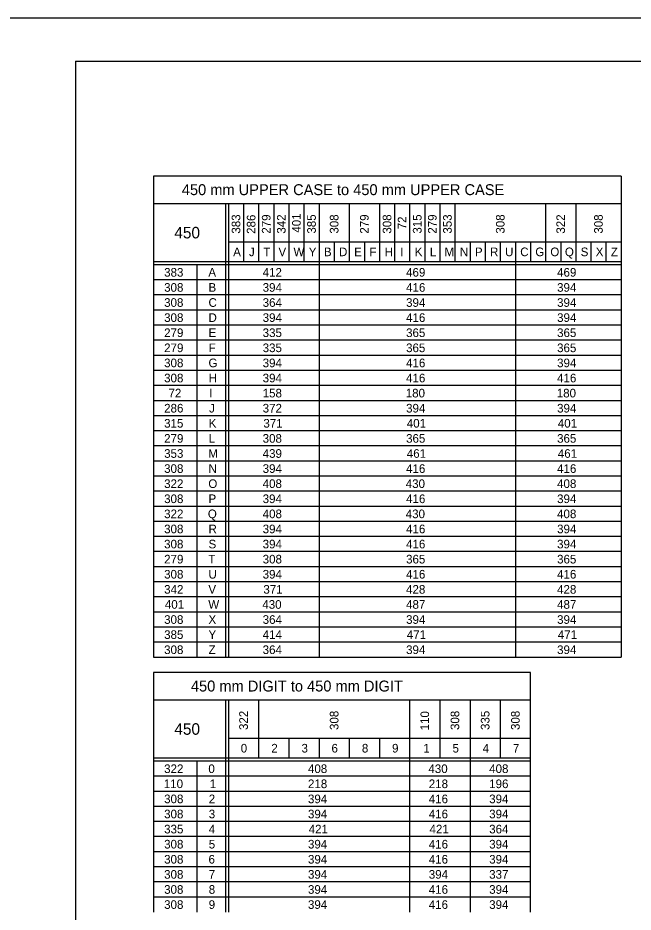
# Model space of a CAD drawing. Extents: x 637580 to 641849, y 297270 to 299646.
# Drawn here: x 638441.3 to 638655.2, y 299334.6 to 299645.6 of the extents above; entities that cross this region are included whole.
import ezdxf

# ---------------------------------------------------------------- set-up
doc = ezdxf.new("R2010")
doc.units = 0
for name, color, linetype in [('1', 7, 'Continuous'), ('2', 7, 'Continuous'), ('XCS-GRID-HVGL', 7, 'Continuous')]:
    doc.layers.add(name, color=color, linetype=linetype)

msp = doc.modelspace()

# ---------------------------------------------------------------- linework, layer by layer
at = {"layer": '1'}
for q in [(639247.31, 299630.63), (638461.31, 299066.63)]:
    msp.add_line((638461.31, 299630.63), q, dxfattribs=at)
at = {"layer": '2'}
for p, q in [((638651.01, 299590.63), (638488.51, 299590.63)), ((638488.51, 299590.63), (638488.51, 299423.25)), ((638651.01, 299590.63), (638651.01, 299423.25)), ((638488.51, 299581.13), (638651.01, 299581.13)), ((638513.51, 299581.13), (638513.51, 299423.25)), ((638514.51, 299581.13), (638514.51, 299423.25)), ((638519.76, 299581.13), (638519.76, 299560.75)), ((638525.01, 299581.13), (638525.01, 299560.75)), ((638530.26, 299581.13), (638530.26, 299560.75)), ((638535.51, 299581.13), (638535.51, 299560.75)), ((638540.76, 299581.13), (638540.76, 299560.75)), ((638546.01, 299581.13), (638546.01, 299423.25)), ((638556.51, 299581.13), (638556.51, 299560.75)), ((638567.01, 299581.13), (638567.01, 299560.75)), ((638572.26, 299581.13), (638572.26, 299560.75)), ((638577.51, 299581.13), (638577.51, 299560.75)), ((638582.76, 299581.13), (638582.76, 299560.75)), ((638588.01, 299581.13), (638588.01, 299560.75)), ((638593.26, 299581.13), (638593.26, 299560.75)), ((638624.76, 299581.13), (638624.76, 299560.75)), ((638635.26, 299581.13), (638635.26, 299560.75)), ((638514.51, 299567.75), (638651.01, 299567.75)), ((638551.26, 299567.75), (638551.26, 299560.75)), ((638561.76, 299567.75), (638561.76, 299560.75)), ((638598.51, 299567.75), (638598.51, 299560.75)), ((638603.76, 299567.75), (638603.76, 299560.75)), ((638609.01, 299567.75), (638609.01, 299560.75)), ((638609.01, 299567.75), (638609.01, 299560.75)), ((638614.26, 299567.75), (638614.26, 299423.25)), ((638619.51, 299567.75), (638619.51, 299560.75)), ((638630.01, 299567.75), (638630.01, 299560.75)), ((638640.51, 299567.75), (638640.51, 299560.75)), ((638645.76, 299567.75), (638645.76, 299560.75)), ((638651.01, 299560.75), (638488.51, 299560.75)), ((638651.01, 299559.75), (638488.51, 299559.75)), ((638503.51, 299559.75), (638503.51, 299423.25)), ((638651.01, 299554.5), (638488.51, 299554.5)), ((638651.01, 299549.25), (638488.51, 299549.25)), ((638651.01, 299544), (638488.51, 299544)), ((638651.01, 299538.75), (638488.51, 299538.75)), ((638651.01, 299533.5), (638488.51, 299533.5)), ((638651.01, 299528.25), (638488.51, 299528.25)), ((638651.01, 299523), (638488.51, 299523)), ((638651.01, 299517.75), (638488.51, 299517.75)), ((638651.01, 299512.5), (638488.51, 299512.5)), ((638651.01, 299507.25), (638488.51, 299507.25)), ((638651.01, 299502), (638488.51, 299502)), ((638651.01, 299496.75), (638488.51, 299496.75)), ((638651.01, 299491.5), (638488.51, 299491.5)), ((638651.01, 299486.25), (638488.51, 299486.25)), ((638651.01, 299481), (638488.51, 299481)), ((638651.01, 299475.75), (638488.51, 299475.75)), ((638651.01, 299470.5), (638488.51, 299470.5)), ((638651.01, 299465.25), (638488.51, 299465.25)), ((638651.01, 299460), (638488.51, 299460)), ((638651.01, 299454.75), (638488.51, 299454.75)), ((638651.01, 299449.5), (638488.51, 299449.5)), ((638651.01, 299444.25), (638488.51, 299444.25)), ((638651.01, 299439), (638488.51, 299439)), ((638651.01, 299433.75), (638488.51, 299433.75)), ((638651.01, 299428.5), (638488.51, 299428.5)), ((638488.51, 299423.25), (638488.51, 299423.25)), ((638488.51, 299423.25), (638651.01, 299423.25)), ((638619.51, 299418), (638488.51, 299418)), ((638488.51, 299418), (638488.51, 299334.63)), ((638619.51, 299334.63), (638619.51, 299418)), ((638488.51, 299408.5), (638619.51, 299408.5)), ((638513.51, 299408.5), (638513.51, 299334.63)), ((638514.51, 299408.5), (638514.51, 299334.63)), ((638525.01, 299408.5), (638525.01, 299388.13)), ((638577.51, 299408.5), (638577.51, 299334.63)), ((638588.01, 299408.5), (638588.01, 299388.13)), ((638598.51, 299408.5), (638598.51, 299334.63)), ((638609.01, 299408.5), (638609.01, 299388.13)), ((638514.51, 299395.13), (638619.51, 299395.13)), ((638535.51, 299395.13), (638535.51, 299388.13)), ((638546.01, 299395.13), (638546.01, 299388.13)), ((638556.51, 299395.13), (638556.51, 299388.13)), ((638567.01, 299395.13), (638567.01, 299388.13)), ((638619.51, 299388.13), (638488.51, 299388.13)), ((638619.51, 299387.13), (638488.51, 299387.13)), ((638503.51, 299387.13), (638503.51, 299334.63)), ((638619.51, 299381.88), (638488.51, 299381.88)), ((638619.51, 299376.63), (638488.51, 299376.63)), ((638619.51, 299371.38), (638488.51, 299371.38)), ((638619.51, 299366.13), (638488.51, 299366.13)), ((638619.51, 299360.88), (638488.51, 299360.88)), ((638619.51, 299355.63), (638488.51, 299355.63)), ((638619.51, 299350.38), (638488.51, 299350.38)), ((638619.51, 299345.13), (638488.51, 299345.13)), ((638619.51, 299339.88), (638488.51, 299339.88))]:
    msp.add_line(p, q, dxfattribs=at)
at = {"layer": 'XCS-GRID-HVGL'}
msp.add_lwpolyline([(638421.31, 299645.63), (639262.31, 299645.63), (639262.31, 299051.63), (638421.31, 299051.63)], close=True, dxfattribs=at)

# ---------------------------------------------------------------- texts
at = {"layer": '2'}
for s, height, p in [('450 mm UPPER CASE to 450 mm UPPER CASE', 3.8, (638498.3, 299583.98)), ('450', 4, (638495.7, 299568.94)), ('A', 3, (638516.16, 299562.75)), ('J', 3, (638521.64, 299562.75)), ('T', 3, (638526.64, 299562.75)), ('V', 3, (638531.91, 299562.75)), ('W', 3, (638537.13, 299562.75)), ('Y', 3, (638542.44, 299562.75)), ('B', 3, (638547.7, 299562.75)), ('D', 3, (638552.95, 299562.75)), ('E', 3, (638558.22, 299562.75)), ('F', 3, (638563.52, 299562.75)), ('H', 3, (638568.79, 299562.75)), ('I', 3, (638574.2, 299562.75)), ('K', 3, (638579.29, 299562.75)), ('L', 3, (638584.54, 299562.75)), ('M', 3, (638589.63, 299562.75)), ('N', 3, (638594.95, 299562.75)), ('P', 3, (638600.2, 299562.75)), ('R', 3, (638605.45, 299562.75)), ('U', 3, (638610.69, 299562.75)), ('C', 3, (638615.95, 299562.75)), ('G', 3, (638621.2, 299562.75)), ('O', 3, (638626.41, 299562.75)), ('Q', 3, (638631.48, 299562.75)), ('S', 3, (638636.97, 299562.75)), ('X', 3, (638642.19, 299562.75)), ('Z', 3, (638647.45, 299562.75)), ('383', 3, (638492.16, 299555.63)), ('A', 3, (638507.53, 299555.63)), ('412', 3, (638526.41, 299555.63)), ('469', 3, (638576.27, 299555.63)), ('469', 3, (638628.77, 299555.63)), ('308', 3, (638492.16, 299550.38)), ('B', 3, (638507.58, 299550.38)), ('394', 3, (638526.41, 299550.38)), ('416', 3, (638576.27, 299550.38)), ('394', 3, (638628.77, 299550.38)), ('308', 3, (638492.16, 299545.13)), ('C', 3, (638507.58, 299545.13)), ('364', 3, (638526.41, 299545.13)), ('394', 3, (638576.27, 299545.13)), ('394', 3, (638628.77, 299545.13)), ('308', 3, (638492.16, 299539.88)), ('D', 3, (638507.58, 299539.88)), ('394', 3, (638526.41, 299539.88)), ('416', 3, (638576.27, 299539.88)), ('394', 3, (638628.77, 299539.88)), ('279', 3, (638492.16, 299534.63)), ('E', 3, (638507.59, 299534.63)), ('335', 3, (638526.41, 299534.63)), ('365', 3, (638576.27, 299534.63)), ('365', 3, (638628.77, 299534.63)), ('279', 3, (638492.16, 299529.38)), ('F', 3, (638507.65, 299529.38)), ('335', 3, (638526.41, 299529.38)), ('365', 3, (638576.27, 299529.38)), ('365', 3, (638628.77, 299529.38)), ('308', 3, (638492.16, 299524.13)), ('G', 3, (638507.58, 299524.13)), ('394', 3, (638526.41, 299524.13)), ('416', 3, (638576.27, 299524.13)), ('394', 3, (638628.77, 299524.13)), ('308', 3, (638492.16, 299518.88)), ('H', 3, (638507.66, 299518.88)), ('394', 3, (638526.41, 299518.88)), ('416', 3, (638576.27, 299518.88)), ('416', 3, (638628.77, 299518.88)), ('72', 3, (638493.66, 299513.63)), ('I', 3, (638507.83, 299513.63)), ('158', 3, (638526.41, 299513.63)), ('180', 3, (638576.15, 299513.63)), ('180', 3, (638628.65, 299513.63)), ('286', 3, (638492.16, 299508.38)), ('J', 3, (638507.77, 299508.38)), ('372', 3, (638526.41, 299508.38)), ('394', 3, (638576.27, 299508.38)), ('394', 3, (638628.77, 299508.38)), ('315', 3, (638492.16, 299503.13)), ('K', 3, (638507.66, 299503.13)), ('371', 3, (638526.66, 299503.13)), ('401', 3, (638576.52, 299503.13)), ('401', 3, (638629.02, 299503.13)), ('279', 3, (638492.16, 299497.88)), ('L', 3, (638507.66, 299497.88)), ('308', 3, (638526.41, 299497.88)), ('365', 3, (638576.27, 299497.88)), ('365', 3, (638628.77, 299497.88)), ('353', 3, (638492.16, 299492.63)), ('M', 3, (638507.51, 299492.63)), ('439', 3, (638526.41, 299492.63)), ('461', 3, (638576.52, 299492.63)), ('461', 3, (638629.02, 299492.63)), ('308', 3, (638492.16, 299487.38)), ('N', 3, (638507.58, 299487.38)), ('394', 3, (638526.41, 299487.38)), ('416', 3, (638576.27, 299487.38)), ('416', 3, (638628.77, 299487.38)), ('322', 3, (638492.16, 299482.13)), ('O', 3, (638507.53, 299482.13)), ('408', 3, (638526.41, 299482.13)), ('430', 3, (638576.15, 299482.13)), ('408', 3, (638628.77, 299482.13)), ('308', 3, (638492.16, 299476.88)), ('P', 3, (638507.58, 299476.88)), ('394', 3, (638526.41, 299476.88)), ('416', 3, (638576.27, 299476.88)), ('394', 3, (638628.77, 299476.88)), ('322', 3, (638492.16, 299471.63)), ('Q', 3, (638507.35, 299471.63)), ('408', 3, (638526.41, 299471.63)), ('430', 3, (638576.15, 299471.63)), ('408', 3, (638628.77, 299471.63)), ('308', 3, (638492.16, 299466.38)), ('R', 3, (638507.58, 299466.38)), ('394', 3, (638526.41, 299466.38)), ('416', 3, (638576.27, 299466.38)), ('394', 3, (638628.77, 299466.38)), ('308', 3, (638492.16, 299461.13)), ('S', 3, (638507.59, 299461.13)), ('394', 3, (638526.41, 299461.13)), ('416', 3, (638576.27, 299461.13)), ('394', 3, (638628.77, 299461.13)), ('279', 3, (638492.16, 299455.88)), ('T', 3, (638507.52, 299455.88)), ('308', 3, (638526.41, 299455.88)), ('365', 3, (638576.27, 299455.88)), ('365', 3, (638628.77, 299455.88)), ('308', 3, (638492.16, 299450.63)), ('U', 3, (638507.57, 299450.63)), ('394', 3, (638526.41, 299450.63)), ('416', 3, (638576.27, 299450.63)), ('416', 3, (638628.77, 299450.63)), ('342', 3, (638492.16, 299445.38)), ('V', 3, (638507.53, 299445.38)), ('371', 3, (638526.66, 299445.38)), ('428', 3, (638576.27, 299445.38)), ('428', 3, (638628.77, 299445.38)), ('401', 3, (638492.41, 299440.13)), ('W', 3, (638507.51, 299440.13)), ('430', 3, (638526.29, 299440.13)), ('487', 3, (638576.27, 299440.13)), ('487', 3, (638628.77, 299440.13)), ('308', 3, (638492.16, 299434.88)), ('X', 3, (638507.57, 299434.88)), ('364', 3, (638526.41, 299434.88)), ('394', 3, (638576.27, 299434.88)), ('394', 3, (638628.77, 299434.88)), ('385', 3, (638492.16, 299429.63)), ('Y', 3, (638507.57, 299429.63)), ('414', 3, (638526.41, 299429.63)), ('471', 3, (638576.52, 299429.63)), ('471', 3, (638629.02, 299429.63)), ('308', 3, (638492.16, 299424.38)), ('Z', 3, (638507.58, 299424.38)), ('364', 3, (638526.41, 299424.38)), ('394', 3, (638576.27, 299424.38)), ('394', 3, (638628.77, 299424.38)), ('450 mm DIGIT to 450 mm DIGIT', 3.8, (638501.46, 299411.35)), ('450', 4, (638495.7, 299396.31)), ('0', 3, (638518.78, 299390.13)), ('2', 3, (638529.41, 299390.13)), ('3', 3, (638539.91, 299390.13)), ('6', 3, (638550.33, 299390.13)), ('8', 3, (638560.91, 299390.13)), ('9', 3, (638571.4, 299390.13)), ('1', 3, (638582.25, 299390.13)), ('5', 3, (638592.41, 299390.13)), ('4', 3, (638602.91, 299390.13)), ('7', 3, (638613.41, 299390.13)), ('322', 3, (638492.16, 299383)), ('0', 3, (638507.53, 299383)), ('408', 3, (638542.16, 299383)), ('430', 3, (638584.03, 299383)), ('408', 3, (638605.16, 299383)), ('110', 3, (638492.04, 299377.75)), ('1', 3, (638508, 299377.75)), ('218', 3, (638542.16, 299377.75)), ('218', 3, (638584.16, 299377.75)), ('196', 3, (638605.16, 299377.75)), ('308', 3, (638492.16, 299372.5)), ('2', 3, (638507.66, 299372.5)), ('394', 3, (638542.16, 299372.5)), ('416', 3, (638584.16, 299372.5)), ('394', 3, (638605.16, 299372.5)), ('308', 3, (638492.16, 299367.25)), ('3', 3, (638507.66, 299367.25)), ('394', 3, (638542.16, 299367.25)), ('416', 3, (638584.16, 299367.25)), ('394', 3, (638605.16, 299367.25)), ('335', 3, (638492.16, 299362)), ('4', 3, (638507.66, 299362)), ('421', 3, (638542.41, 299362)), ('421', 3, (638584.41, 299362)), ('364', 3, (638605.16, 299362)), ('308', 3, (638492.16, 299356.75)), ('5', 3, (638507.66, 299356.75)), ('394', 3, (638542.16, 299356.75)), ('416', 3, (638584.16, 299356.75)), ('394', 3, (638605.16, 299356.75)), ('308', 3, (638492.16, 299351.5)), ('6', 3, (638507.58, 299351.5)), ('394', 3, (638542.16, 299351.5)), ('416', 3, (638584.16, 299351.5)), ('394', 3, (638605.16, 299351.5)), ('308', 3, (638492.16, 299346.25)), ('7', 3, (638507.66, 299346.25)), ('394', 3, (638542.16, 299346.25)), ('394', 3, (638584.16, 299346.25)), ('337', 3, (638605.16, 299346.25)), ('308', 3, (638492.16, 299341)), ('8', 3, (638507.66, 299341)), ('394', 3, (638542.16, 299341)), ('416', 3, (638584.16, 299341)), ('394', 3, (638605.16, 299341)), ('308', 3, (638492.16, 299335.75)), ('9', 3, (638507.65, 299335.75)), ('394', 3, (638542.16, 299335.75)), ('416', 3, (638584.16, 299335.75)), ('394', 3, (638605.16, 299335.75))]:
    msp.add_text(s, height=height, dxfattribs=at).set_placement(p)
for s, p in [('383', (638518.64, 299570.59)), ('279', (638529.14, 299570.58)), ('342', (638534.39, 299570.59)), ('401', (638539.64, 299570.93)), ('385', (638544.89, 299570.59)), ('308', (638552.76, 299570.59)), ('279', (638563.26, 299570.58)), ('308', (638571.14, 299570.59)), ('315', (638581.64, 299570.59)), ('279', (638586.89, 299570.58)), ('353', (638592.14, 299570.59)), ('308', (638610.51, 299570.59)), ('322', (638631.51, 299570.59)), ('308', (638644.64, 299570.59)), ('286', (638523.89, 299570.51)), ('72', (638576.39, 299572.09)), ('322', (638521.26, 299397.96)), ('308', (638552.76, 299397.96)), ('110', (638584.26, 299397.83)), ('308', (638594.76, 299397.96)), ('335', (638605.26, 299397.96)), ('308', (638615.76, 299397.96))]:
    msp.add_text(s, height=3, rotation=90, dxfattribs=at).set_placement(p)

doc.saveas('drawing.dxf')
